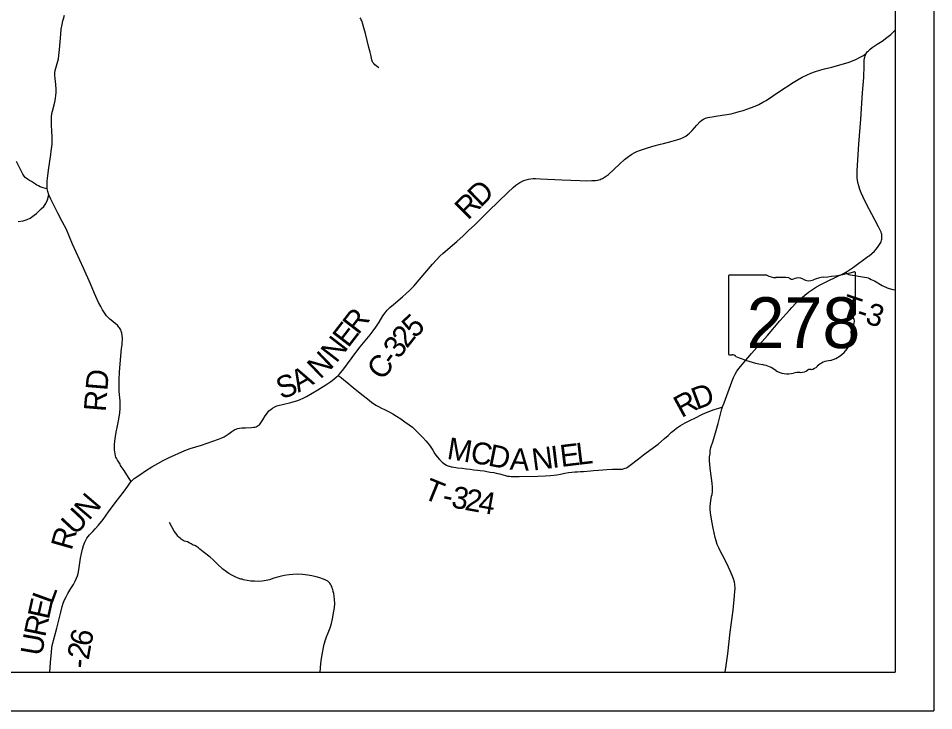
# Model space of a CAD drawing. Extents: x 0 to 34, y 0 to 22.
# Drawn here: x 6.504 to 8.876, y 14.105 to 15.901 of the extents above; entities that cross this region are included whole.
import ezdxf

# ---------------------------------------------------------------- set-up
doc = ezdxf.new("R2010")
doc.units = 0
for name, color, linetype in [('GM_X_County_Road', 7, 'Continuous'), ('GM_X_County_Road_Text', 7, 'Continuous'), ('GM_X_State_Location', 7, 'Continuous'), ('GM_X_State_Route', 7, 'Continuous'), ('GM_X_State_Shield', 7, 'Continuous'), ('GM_X_Township_Road', 7, 'Continuous'), ('GM_X_Township_Road_Text', 7, 'Continuous'), ('SH_Data', 7, 'Continuous')]:
    doc.layers.add(name, color=color, linetype=linetype)

msp = doc.modelspace()

# ---------------------------------------------------------------- linework, layer by layer
at = {"layer": 'GM_X_County_Road'}
for points in [[(6.5857, 14.2054), (6.588, 14.2305), (6.5899, 14.2569), (6.5911, 14.2682), (6.5924, 14.2742), (6.6039, 14.3191), (6.6142, 14.3612), (6.618, 14.3757), (6.6208, 14.3843), (6.6241, 14.3928), (6.628, 14.4011), (6.6325, 14.4092), (6.6407, 14.4222), (6.6472, 14.4328), (6.6516, 14.441), (6.6554, 14.4495), (6.6574, 14.4554), (6.6591, 14.4614), (6.661, 14.4706), (6.6656, 14.5012), (6.6677, 14.5129), (6.6705, 14.5247), (6.6732, 14.5335), (6.6765, 14.5422), (6.6791, 14.5477), (6.6821, 14.5531), (6.6849, 14.5569), (6.6887, 14.5616), (6.6975, 14.57), (6.7038, 14.5766), (6.7122, 14.5862), (6.7239, 14.601), (6.7306, 14.6101), (6.7399, 14.6234), (6.7428, 14.6277), (6.7579, 14.648), (6.777, 14.6725), (6.7881, 14.6876), (6.7934, 14.6953), (6.7968, 14.7), (6.7902, 14.7105), (6.7782, 14.7283), (6.7712, 14.739), (6.7692, 14.7416), (6.7678, 14.7443), (6.7631, 14.7523), (6.7617, 14.7549), (6.7587, 14.7599), (6.7573, 14.7628), (6.7562, 14.7659), (6.7549, 14.7714), (6.7534, 14.782), (6.7531, 14.7883), (6.7534, 14.7946), (6.7544, 14.804), (6.7563, 14.8161), (6.7582, 14.8279), (6.7602, 14.8399), (6.7645, 14.8614), (6.7669, 14.8774), (6.768, 14.8893), (6.7684, 14.8982), (6.7678, 14.909), (6.7659, 14.9332), (6.7654, 14.9488), (6.7656, 14.9644), (6.7665, 14.9829), (6.7679, 15.0045), (6.772, 15.0446), (6.773, 15.0537), (6.7736, 15.0609), (6.774, 15.0659), (6.774, 15.0726), (6.7736, 15.0785), (6.7727, 15.084), (6.771, 15.0898), (6.7698, 15.0926), (6.7684, 15.0953), (6.7668, 15.0979), (6.765, 15.1003), (6.763, 15.1026), (6.7609, 15.1047), (6.7562, 15.1086), (6.7488, 15.1144), (6.7417, 15.1205), (6.7373, 15.125), (6.7332, 15.1297), (6.7294, 15.1347), (6.7225, 15.1451), (6.7178, 15.1532), (6.7121, 15.1643), (6.7015, 15.1868), (6.6913, 15.2123), (6.6732, 15.2527), (6.6449, 15.3152), (6.6288, 15.353), (6.6177, 15.3743), (6.6064, 15.3953), (6.5976, 15.4126), (6.5885, 15.4319), (6.5837, 15.4434), (6.5809, 15.4517), (6.5793, 15.4585), (6.5789, 15.4604), (6.5786, 15.4667), (6.5788, 15.4729), (6.5793, 15.4781), (6.58, 15.4853), (6.5827, 15.507), (6.5888, 15.5478), (6.5897, 15.5563), (6.5903, 15.5622), (6.5918, 15.5744), (6.5922, 15.5805), (6.5919, 15.5928), (6.5911, 15.6087), (6.5903, 15.6226), (6.59, 15.6352), (6.5903, 15.6444), (6.5914, 15.6539), (6.5926, 15.6597), (6.5987, 15.6832), (6.6006, 15.6924), (6.6019, 15.7014), (6.6023, 15.7074), (6.6023, 15.7163), (6.6011, 15.7289), (6.5996, 15.7444), (6.5992, 15.7536), (6.5993, 15.7594), (6.6, 15.7655), (6.6011, 15.7718), (6.6028, 15.7779), (6.6067, 15.7895), (6.6082, 15.7953), (6.6096, 15.8044), (6.6112, 15.8197), (6.6143, 15.86), (6.6156, 15.8723), (6.6176, 15.8846), (6.6194, 15.8938), (6.6211, 15.8998), (6.6242, 15.9087)], [(6.7968, 14.7), (6.8048, 14.7071), (6.8188, 14.7174), (6.8342, 14.7278), (6.85, 14.7375), (6.8661, 14.7468), (6.8798, 14.7541), (6.8937, 14.7608), (6.9359, 14.7797), (6.95, 14.7851), (6.9786, 14.7941), (7.0083, 14.8039), (7.023, 14.8092), (7.0317, 14.8128), (7.0373, 14.8156), (7.0454, 14.8204), (7.0505, 14.8239), (7.0573, 14.8293), (7.0603, 14.8314), (7.0629, 14.833), (7.0655, 14.8343), (7.0688, 14.8358), (7.0724, 14.8369), (7.0773, 14.838), (7.0836, 14.8388), (7.0927, 14.8392), (7.1081, 14.8397), (7.1144, 14.8403), (7.1175, 14.8409), (7.1205, 14.8419), (7.1234, 14.8432), (7.1261, 14.8447), (7.1289, 14.8467), (7.1313, 14.8493), (7.1331, 14.8519), (7.1346, 14.8544), (7.1379, 14.8597), (7.1443, 14.8704), (7.1497, 14.8779), (7.1537, 14.8826), (7.1582, 14.8867), (7.1632, 14.89), (7.1689, 14.8933), (7.1745, 14.8959), (7.1811, 14.8981), (7.1892, 14.8997), (7.2104, 14.9044), (7.2195, 14.9068), (7.2284, 14.9096), (7.2342, 14.912), (7.2426, 14.916), (7.2509, 14.9204), (7.2803, 14.9378), (7.3015, 14.9506), (7.3145, 14.9592), (7.322, 14.9648), (7.3292, 14.9708), (7.3332, 14.9748), (7.3358, 14.9774), (7.3399, 14.9821), (7.3477, 14.9919), (7.3791, 15.0343), (7.3904, 15.049), (7.4161, 15.0801), (7.4237, 15.09), (7.4309, 15.1002), (7.4393, 15.1133), (7.449, 15.1293), (7.4545, 15.1373), (7.4604, 15.1442), (7.467, 15.1506), (7.4761, 15.1587), (7.4999, 15.1786), (7.5092, 15.1868), (7.5183, 15.1954), (7.529, 15.2066), (7.5434, 15.223), (7.5773, 15.2634), (7.5877, 15.2748), (7.5964, 15.2836), (7.6055, 15.292), (7.641, 15.3223), (7.6569, 15.3371), (7.6721, 15.3514), (7.686, 15.3647), (7.7237, 15.4016), (7.7728, 15.449), (7.7864, 15.4617), (7.7934, 15.4677), (7.7984, 15.4714), (7.8035, 15.4747), (7.8089, 15.4775), (7.8146, 15.4799), (7.8204, 15.4819), (7.8263, 15.4835), (7.8324, 15.4845), (7.8385, 15.485), (7.8446, 15.4851), (7.857, 15.4848), (7.9128, 15.4821), (7.9593, 15.48), (7.9779, 15.4797), (7.9904, 15.4798), (7.9997, 15.4805), (8.0059, 15.4815), (8.012, 15.4831), (8.015, 15.4842), (8.0179, 15.4855), (8.0234, 15.4885), (8.0285, 15.4921), (8.0333, 15.4961), (8.0617, 15.5223), (8.0755, 15.5346), (8.0853, 15.5424), (8.0939, 15.5484), (8.1003, 15.5519), (8.1071, 15.555), (8.1168, 15.5591), (8.1292, 15.5634), (8.1485, 15.569), (8.1687, 15.5746), (8.1765, 15.5765), (8.1988, 15.5822), (8.2104, 15.5853), (8.2194, 15.5885), (8.2274, 15.592), (8.2336, 15.5954), (8.2388, 15.5992), (8.2437, 15.6031), (8.2504, 15.6096), (8.2627, 15.6239), (8.2711, 15.633), (8.2757, 15.6369), (8.28, 15.6396), (8.2851, 15.642), (8.2913, 15.6438), (8.2963, 15.6448), (8.3019, 15.6455), (8.3172, 15.6475), (8.3513, 15.6534), (8.3636, 15.6562), (8.3726, 15.6588), (8.3823, 15.6616), (8.392, 15.6648), (8.4141, 15.6733), (8.4228, 15.6772), (8.4339, 15.683), (8.4419, 15.6878), (8.4754, 15.7103), (8.5118, 15.7339), (8.525, 15.7419), (8.5358, 15.7478), (8.5469, 15.7532), (8.5583, 15.7581), (8.5698, 15.7625), (8.5816, 15.7663), (8.5936, 15.7695), (8.6125, 15.7742), (8.6329, 15.7797), (8.6545, 15.7863), (8.6698, 15.7918), (8.6764, 15.7948), (8.6827, 15.798), (8.6872, 15.8006), (8.694, 15.8045), (8.699, 15.8077), (8.7015, 15.8093)]]:
    msp.add_lwpolyline(points, dxfattribs=at)
at = {"layer": 'GM_X_State_Route'}
msp.add_lwpolyline([(8.3356, 14.2054), (8.3393, 14.2286), (8.3425, 14.2532), (8.3491, 14.3088), (8.3567, 14.3659), (8.36, 14.403), (8.3611, 14.4152), (8.3616, 14.4212), (8.3617, 14.4255), (8.3614, 14.4292), (8.3609, 14.4338), (8.3599, 14.4388), (8.3573, 14.4477), (8.3541, 14.4563), (8.3492, 14.4677), (8.34, 14.4873), (8.329, 14.5091), (8.3231, 14.5196), (8.3191, 14.528), (8.3155, 14.5366), (8.3124, 14.5455), (8.3101, 14.5545), (8.3047, 14.5789), (8.3013, 14.5972), (8.2982, 14.6185), (8.2974, 14.6278), (8.2973, 14.634), (8.298, 14.6433), (8.2988, 14.6495), (8.3009, 14.6617), (8.3019, 14.6663), (8.3029, 14.6737), (8.3033, 14.6801), (8.3033, 14.6846), (8.3033, 14.6851), (8.3024, 14.695), (8.2979, 14.7273), (8.2962, 14.7442), (8.2957, 14.7535), (8.2957, 14.7634), (8.2967, 14.7711), (8.2974, 14.7791), (8.2991, 14.7881), (8.3049, 14.805), (8.3146, 14.8384), (8.3175, 14.8498), (8.3186, 14.854), (8.3228, 14.8707), (8.3277, 14.8881), (8.3293, 14.8937), (8.3332, 14.9038), (8.3529, 14.9581), (8.3578, 14.9696), (8.3619, 14.9781), (8.3666, 14.9862), (8.372, 14.9938), (8.3799, 15.0035), (8.4041, 15.0316), (8.4454, 15.0782), (8.4777, 15.1161), (8.5026, 15.1441), (8.5086, 15.1509), (8.5193, 15.1622), (8.5282, 15.1709), (8.5424, 15.1829), (8.5521, 15.1906), (8.5623, 15.1978), (8.5729, 15.2045), (8.5838, 15.2106), (8.6032, 15.2204), (8.6424, 15.2392), (8.6484, 15.2425), (8.6505, 15.2436), (8.6584, 15.2485), (8.6685, 15.2556), (8.7056, 15.2828), (8.7088, 15.2851), (8.716, 15.2911), (8.7227, 15.2974), (8.727, 15.3018), (8.7309, 15.3065), (8.7345, 15.3114), (8.7376, 15.3167), (8.7389, 15.3194), (8.7401, 15.3223), (8.741, 15.3251), (8.7417, 15.3281), (8.7422, 15.3311), (8.7423, 15.3341), (8.7422, 15.3371), (8.7418, 15.3401), (8.7411, 15.343), (8.7401, 15.3459), (8.7378, 15.3515), (8.7335, 15.3598), (8.7156, 15.3925), (8.7028, 15.4173), (8.6932, 15.4369), (8.6882, 15.4483), (8.685, 15.4571), (8.6821, 15.466), (8.6798, 15.4751), (8.6787, 15.4813), (8.6779, 15.4875), (8.6778, 15.4932), (8.6779, 15.4993), (8.6783, 15.5063), (8.6827, 15.5744), (8.6878, 15.6393), (8.6921, 15.7075), (8.6949, 15.7477), (8.6961, 15.7786), (8.6965, 15.7911), (8.6973, 15.7973), (8.6979, 15.8004), (8.6989, 15.8035), (8.7, 15.8064), (8.7015, 15.8093), (8.7032, 15.812), (8.7052, 15.8145), (8.7074, 15.8168), (8.712, 15.821), (8.7169, 15.8249), (8.7299, 15.8335), (8.7429, 15.8418), (8.7553, 15.8506), (8.7649, 15.8588), (8.7717, 15.8651), (8.7763, 15.87)], dxfattribs=at)
at = {"layer": 'GM_X_State_Shield'}
for p, q in [((8.3442, 15.2316), (8.3442, 15.0315)), ((8.444, 15.2351), (8.3475, 15.2351)), ((8.6738, 15.1353), (8.6738, 15.24)), ((8.6738, 15.1354), (8.6738, 15.1353))]:
    msp.add_line(p, q, dxfattribs=at)
for centre, major_axis, start_param, end_param in [((8.348, 15.232), (0.00382, 0), 1.712693, 3.28349), ((8.467, 15.2583), (0.037, 0), 4.042523, 4.731795), ((8.4792, 15.1227), (0.133, 0), 1.404758, 1.657858), ((8.5251, 15.21), (0.0222, 0), 0.950623, 2.079405), ((8.601, 15.1739), (0.0703, 0), 1.699011, 2.107814), ((8.5564, 15.5079), (0.3495, 0), 4.814394, 5.042369), ((8.6701, 15.2405), (0.00367, 0), 6.141152, 7.989035), ((8.5094, 15.2331), (0.0107, 0), 3.836095, 5.185415), ((8.5538, 15.2417), (0.0267, 0), 4.081561, 5.145723), ((8.6699, 15.1349), (0.00393, 0), 5.05454, 6.418171), ((8.6729, 15.1277), (0.00568, 0), 1.883978, 3.671073), ((8.6368, 15.1144), (0.0341, 0), 5.934695, 6.695948), ((8.576, 15.0782), (0.0874, 0), 5.101752, 6.440018), ((8.6869, 15.0915), (0.0248, 0), 2.387724, 3.262537), ((8.348, 15.0311), (0.00385, 0), 3.00124, 4.508301), ((8.3486, 15.0515), (0.0294, 0), 4.665946, 4.897461), ((8.3546, 15.02), (0.0106, 0), 0.519207, 1.627899), ((8.4884, 15.1998), (0.2524, 0), 4.195997, 4.488961), ((8.4132, 14.9416), (0.079, 0), 0.823519, 1.323587), ((8.5522, 15.0121), (0.0282, 0), 4.937069, 5.64225), ((8.6128, 14.9753), (0.0479, 0), 1.647645, 2.488434), ((8.4986, 15.019), (0.0501, 0), 4.026481, 4.996735), ((8.5276, 14.9498), (0.0412, 0), 1.495662, 1.94098), ((8.5312, 15.004), (0.0267, 0), 4.691044, 5.507374), ((8.5554, 14.9846), (0.00752, 0), 1.147584, 2.315152)]:
    msp.add_ellipse(centre, major_axis=major_axis, ratio=0.8, start_param=start_param, end_param=end_param, dxfattribs=at)
at = {"layer": 'GM_X_Township_Road'}
for points in [[(7.4162, 15.8134), (7.4129, 15.8253), (7.4038, 15.8613), (7.3995, 15.8762), (7.3971, 15.8852), (7.3942, 15.894), (7.393, 15.8969), (7.3915, 15.8996), (7.3898, 15.9021)], [(7.4382, 15.7723), (7.4284, 15.7803), (7.4252, 15.7834), (7.4232, 15.7862), (7.4223, 15.7879), (7.4215, 15.7903), (7.4206, 15.7932), (7.418, 15.8061), (7.4162, 15.8134)], [(6.5793, 15.4585), (6.5745, 15.4597), (6.5685, 15.4611), (6.5611, 15.4638), (6.5565, 15.4664), (6.5526, 15.4685), (6.5485, 15.471), (6.5437, 15.4739), (6.538, 15.4774), (6.533, 15.4805), (6.5283, 15.4836), (6.5242, 15.4866), (6.5221, 15.4883), (6.5196, 15.4912), (6.5162, 15.4968), (6.5088, 15.5102), (6.4999, 15.5298)], [(6.5039, 15.374), (6.5164, 15.3758), (6.5275, 15.3788), (6.535, 15.3827), (6.5452, 15.3901), (6.551, 15.395), (6.5549, 15.3983), (6.5639, 15.4071), (6.57, 15.4131), (6.5752, 15.4207), (6.5796, 15.4298), (6.5837, 15.4434)], [(8.6484, 15.2425), (8.6497, 15.2412), (8.6517, 15.2391), (8.6534, 15.2379), (8.6568, 15.2367), (8.6611, 15.2356), (8.6662, 15.2347), (8.6731, 15.2336), (8.6812, 15.2323), (8.6867, 15.2315), (8.6922, 15.2305), (8.6974, 15.2296), (8.703, 15.2284), (8.7063, 15.2275), (8.71, 15.226), (8.7146, 15.2238), (8.7229, 15.2197), (8.7426, 15.2083), (8.7554, 15.202), (8.7612, 15.2001), (8.7702, 15.1979), (8.7763, 15.1969)], [(7.3332, 14.9748), (7.3406, 14.9691), (7.3482, 14.9634), (7.3553, 14.9577), (7.3723, 14.9434), (7.3941, 14.9257), (7.4089, 14.9141), (7.4196, 14.9057), (7.4304, 14.8981), (7.4377, 14.8939), (7.4454, 14.8902), (7.4528, 14.8868), (7.4637, 14.8813), (7.4745, 14.8754), (7.4846, 14.8694), (7.4952, 14.8624), (7.5061, 14.8547), (7.5175, 14.8467), (7.5255, 14.8403), (7.5329, 14.8334), (7.5392, 14.8269), (7.5523, 14.8141), (7.5603, 14.8056), (7.5658, 14.7991), (7.5694, 14.7938), (7.5747, 14.7863), (7.5786, 14.7806), (7.5836, 14.7719), (7.5899, 14.7633), (7.5959, 14.7568), (7.603, 14.7499), (7.6098, 14.7445), (7.6139, 14.7423), (7.6175, 14.7406), (7.62, 14.7396), (7.6213, 14.7391), (7.6255, 14.7381), (7.6287, 14.7375), (7.6426, 14.7355), (7.6546, 14.734), (7.6657, 14.7327), (7.6755, 14.7315), (7.6845, 14.7302), (7.6938, 14.729), (7.7009, 14.7283), (7.7111, 14.7271), (7.7187, 14.7259), (7.7274, 14.7243), (7.7362, 14.7227), (7.7424, 14.7216), (7.7513, 14.7196), (7.7607, 14.7172), (7.7669, 14.7152), (7.7717, 14.714), (7.7771, 14.7132), (7.7815, 14.7126), (7.7893, 14.7124), (7.8017, 14.7123), (7.8506, 14.7135), (7.8691, 14.7141), (7.883, 14.7152), (7.8998, 14.7173), (7.9093, 14.7191), (7.9205, 14.7215), (7.9296, 14.723), (7.9389, 14.7242), (7.9462, 14.7248), (7.9536, 14.7252), (7.9614, 14.7257), (7.9686, 14.726), (7.987, 14.7272), (7.9947, 14.728), (8.0077, 14.7294), (8.019, 14.7301), (8.0297, 14.7308), (8.0441, 14.7315), (8.0558, 14.7313), (8.0649, 14.7316), (8.0701, 14.7321), (8.074, 14.7331), (8.0771, 14.734), (8.0801, 14.7353), (8.0826, 14.7366), (8.0866, 14.7392), (8.097, 14.7471), (8.1159, 14.7622), (8.1246, 14.7692), (8.1277, 14.7716), (8.15, 14.7882), (8.1619, 14.7969), (8.1789, 14.8112), (8.1881, 14.8188), (8.197, 14.8276), (8.2037, 14.8332), (8.2096, 14.8377), (8.22, 14.8448), (8.2322, 14.8518), (8.2444, 14.858), (8.2591, 14.8652), (8.2756, 14.8735), (8.2848, 14.8779), (8.2959, 14.8824), (8.3078, 14.8867), (8.3197, 14.8901), (8.3249, 14.8919), (8.3293, 14.8937)], [(7.2866, 14.2054), (7.2882, 14.2282), (7.2899, 14.2409), (7.2923, 14.2558), (7.2951, 14.2697), (7.2971, 14.2782), (7.3006, 14.2892), (7.3031, 14.2966), (7.3073, 14.3073), (7.3122, 14.3203), (7.3156, 14.3312), (7.3188, 14.3438), (7.3222, 14.3631), (7.3234, 14.3726), (7.3242, 14.3834), (7.3239, 14.3936), (7.3229, 14.4024), (7.3215, 14.4097), (7.3204, 14.4149), (7.3191, 14.4195), (7.3178, 14.4236), (7.3165, 14.4271), (7.3149, 14.4304), (7.3133, 14.4334), (7.3112, 14.4364), (7.3088, 14.4389), (7.306, 14.4413), (7.3011, 14.4441), (7.2949, 14.4468), (7.2857, 14.4499), (7.2761, 14.4527), (7.2651, 14.4551), (7.2542, 14.457), (7.2411, 14.4586), (7.2282, 14.4591), (7.2156, 14.4587), (7.2063, 14.4579), (7.1929, 14.4559), (7.1795, 14.4528), (7.166, 14.4487), (7.1549, 14.4451), (7.1461, 14.4432), (7.1362, 14.4417), (7.1255, 14.4408), (7.1164, 14.4409), (7.1065, 14.4416), (7.0969, 14.443), (7.0877, 14.445), (7.084, 14.4461), (7.0813, 14.4468), (7.0736, 14.4495), (7.0662, 14.4524), (7.0577, 14.4567), (7.0501, 14.4612), (7.0436, 14.4656), (7.0346, 14.4727), (7.0206, 14.4855), (7.009, 14.4965), (7.001, 14.5038), (6.9831, 14.5178), (6.9748, 14.5244), (6.971, 14.5276), (6.9662, 14.531), (6.9617, 14.5336), (6.9577, 14.535), (6.9549, 14.5363), (6.9519, 14.5384), (6.9473, 14.541), (6.9427, 14.5429), (6.9381, 14.5442), (6.9352, 14.5454), (6.9318, 14.5469), (6.9291, 14.5484), (6.9265, 14.5502), (6.9236, 14.5524), (6.9203, 14.5553), (6.9176, 14.5582), (6.9148, 14.562), (6.9085, 14.5709), (6.9017, 14.5825), (6.8963, 14.5938)]]:
    msp.add_lwpolyline(points, dxfattribs=at)
at = {"layer": 'SH_Data'}
for p, q in [((8.8763, 21.1054), (8.8763, 14.1054)), ((8.7763, 21.0054), (8.7763, 14.2054)), ((1.9763, 14.2054), (8.7763, 14.2054)), ((1.8763, 14.1054), (8.8763, 14.1054))]:
    msp.add_line(p, q, dxfattribs=at)

# ---------------------------------------------------------------- texts
at = {"layer": 'GM_X_County_Road_Text'}
for s, height, rotation, p in [('D', 0.0568, 44.3895, (7.7022, 15.4087)), ('R', 0.0568, 44.989, (7.6693, 15.3758)), ('R', 0.0568, 52.3277, (7.385, 15.078)), ('5', 0.0568, 44.0579, (7.5315, 15.0691)), ('E', 0.0568, 52.3323, (7.359, 15.0444)), ('2', 0.0568, 51.8425, (7.5113, 15.0431)), ('N', 0.0568, 52.3117, (7.3285, 15.0048)), ('3', 0.0568, 52.8845, (7.4903, 15.0154)), ('N', 0.0568, 43.961, (7.2864, 14.9634)), ('C', 0.0568, 53.2472, (7.4484, 14.9594)), ('-', 0.0568, 53.152, (7.4764, 14.9968)), ('A', 0.0568, 29.1261, (7.2299, 14.9295)), ('RD', 0.05682, 85.1552, (6.7303, 14.8792)), ('S', 0.0568, 20.1946, (7.1851, 14.9122)), ('N', 0.0568, 49.5635, (6.6875, 14.5966)), ('U', 0.0568, 46.9451, (6.6515, 14.558)), ('R', 0.0568, 74.1071, (6.6422, 14.5192)), ('L', 0.0568, 70.1311, (6.5919, 14.3796)), ('E', 0.0568, 77.3931, (6.5832, 14.3399)), ('R', 0.0568, 78.4153, (6.5739, 14.2945)), ('U', 0.0568, 80.1155, (6.5654, 14.2456)), ('6', 0.0568, 78.6013, (6.6924, 14.2696)), ('2', 0.0568, 80.1262, (6.6865, 14.2355)), ('-', 0.0568, 86.1124, (6.6851, 14.2138))]:
    msp.add_text(s, height=height, rotation=rotation, dxfattribs=at).set_placement(p)
at = {"layer": 'GM_X_State_Location'}
for s in ['s', 'r']:
    msp.add_text(s, height=0.000189, dxfattribs=at).set_placement((8.5053, 15.1183))
msp.add_text('278', height=0.000189, rotation=0, dxfattribs=at).set_placement((8.4384, 15.1045))
at = {"layer": 'GM_X_State_Shield'}
msp.add_text('278', height=0.13184, dxfattribs=at).set_placement((8.3918, 15.0456))
at = {"layer": 'GM_X_Township_Road_Text'}
for s, rotation, p in [('T', 341.0894, (8.6323, 15.1326)), ('3', 343.0238, (8.6966, 15.1107)), ('-', 341.3999, (8.6728, 15.1187)), ('D', 20.5654, (8.2619, 14.8852)), ('R', 28.6425, (8.2228, 14.8637)), ('M', 350.7746, (7.6129, 14.7588)), ('C', 350.7456, (7.6737, 14.7489)), ('D', 348.6293, (7.7192, 14.7415)), ('A', 356.5077, (7.7767, 14.7305)), ('N', 7.5683, (7.8386, 14.7279)), ('I', 6.9256, (7.888, 14.7345)), ('E', 6.9209, (7.9111, 14.7373)), ('L', 6.9252, (7.9533, 14.7424)), ('T', 337.959, (7.55, 14.6573)), ('3', 349.1828, (7.6239, 14.6333)), ('-', 348.6818, (7.6005, 14.638)), ('2', 349.7936, (7.6589, 14.6266)), ('4', 349.9605, (7.6936, 14.6204))]:
    msp.add_text(s, height=0.0568, rotation=rotation, dxfattribs=at).set_placement(p)

doc.saveas('drawing.dxf')
